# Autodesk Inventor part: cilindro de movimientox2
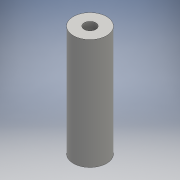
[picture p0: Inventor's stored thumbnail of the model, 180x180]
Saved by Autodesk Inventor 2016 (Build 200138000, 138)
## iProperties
Created: 2016-06
Part Number: cilindro de movimientox2
Material: Genérico
Document SubType Name: Modeling
Designer: adm
Density: 1 g/cm^3
Appearance: Valor por defecto
Author: adm
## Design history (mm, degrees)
sketch "Boceto1"
  geometry: C1 r 15 at (0, 0); 1 further point
  constraints: 1 centre point, 1 coincident
  dimensions: "d0" = 30 diameter of C1
extrude "Extrusión1" new body sketch "Boceto1" distance "d1" = 100; taper "d2" = 0 deg
sketch "Boceto2"
  geometry: C1 r 5.25 at (0, 0); 1 further point
  constraints: 1 centre point, 1 coincident
  dimensions: "d3" = 10.5 diameter of C1
extrude "Extrusión2" cut sketch "Boceto2" distance "d4" = 100; taper "d5" = 0 deg
node "Sólido1"
